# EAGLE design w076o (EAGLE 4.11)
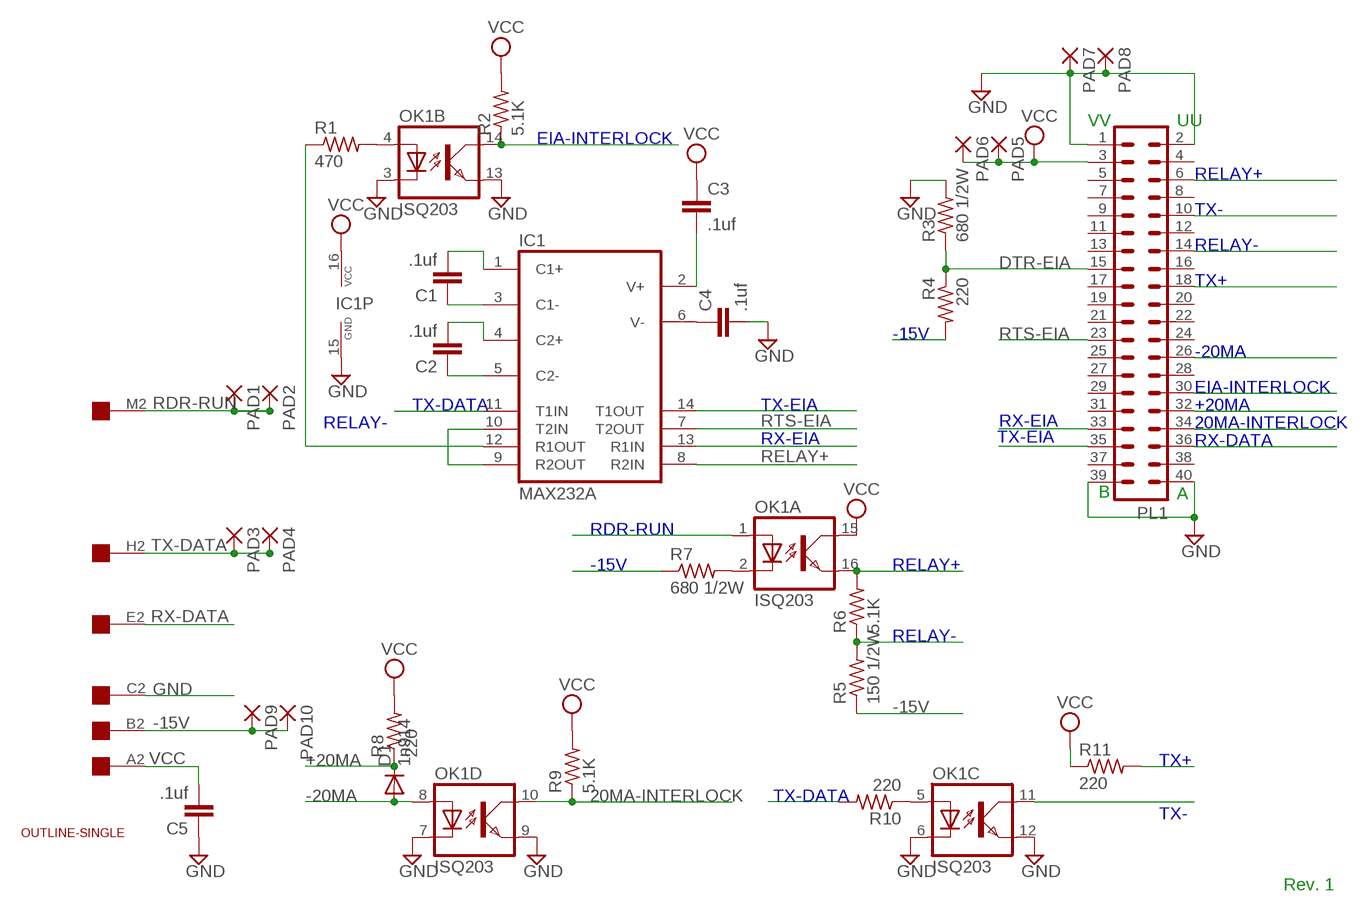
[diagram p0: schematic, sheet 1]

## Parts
C1  .1uf  C-EU050-025X075  [C050-025X075]
C2  .1uf  C-EU050-025X075  [C050-025X075]
C3  .1uf  C-EU050-025X075  [C050-025X075]
C4  .1uf  C-EU050-025X075  [C050-025X075]
C5  .1uf  C-EU050-025X075  [C050-025X075]
D1  1n914  1N4004  [DO41-10]
IC1  MAX232A  MAX232  [DIL16]
OK1  ISQ203  ILQ1  [DIL16]
PAD1  1,6/0,8  [1,6/0,8]
PAD2  1,6/0,8  [1,6/0,8]
PAD3  1,6/0,8  [1,6/0,8]
PAD4  1,6/0,8  [1,6/0,8]
PAD5  1,6/0,8  [1,6/0,8]
PAD6  1,6/0,8  [1,6/0,8]
PAD7  1,6/0,8  [1,6/0,8]
PAD8  1,6/0,8  [1,6/0,8]
PAD9  1,6/0,8  [1,6/0,8]
PAD10  1,6/0,8  [1,6/0,8]
PL1  40H  [40H]
R1  470  R-US_0207/10  [0207/10]
R2  5.1K  R-US_0207/10  [0207/10]
R3  680 1/2W  R-US_0207/12  [0207/12]
R4  220  R-US_0207/10  [0207/10]
R5  150 1/2W  R-US_0207/12  [0207/12]
R6  5.1K  R-US_0207/10  [0207/10]
R7  680 1/2W  R-US_0207/12  [0207/12]
R8  220  R-US_0207/10  [0207/10]
R9  5.1K  R-US_0207/10  [0207/10]
R10  220  R-US_0207/10  [0207/10]
R11  220  R-US_0207/10  [0207/10]
U$1  EDGE-2CONNECTOR  [EDGE-CON2]
U$2  OUTLINE-SINGLE  [SINGLE]

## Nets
20MA-INTERLOCK: OK1.10(D:COL) PL1.34 R9.1
+20MA: D1.C PL1.32 R8.1
-15V [supply]: PAD9.1(P) PAD10.1(P) R4.2 R5.1 R7.1 U$1.B2
-20MA: D1.A OK1.8(D:A) PL1.26
DTR-EIA: PL1.15 R3.1 R4.1
EIA-INTERLOCK: OK1.14(B:COL) PL1.30 R2.1
GND [supply]: C4.2 C5.1 IC1.15(GND) OK1.3(B:C) OK1.6(C:C) OK1.7(D:C) OK1.9(D:EMIT) OK1.12(C:EMIT) OK1.13(B:EMIT) PAD7.1(P) PAD8.1(P) PL1.1 PL1.2 PL1.39 PL1.40 R3.2 U$1.C2
N$1: C2.1 IC1.5(C2-)
N$2: C2.2 IC1.4(C2+)
N$3: C1.2 IC1.1(C1+)
N$4: C1.1 IC1.3(C1-)
N$5: OK1.2(A:C) R7.2
N$6: IC1.9(R2OUT) IC1.10(T2IN)
N$8: IC1.12(R1OUT) R1.1
N$9: C3.2 IC1.2(V+)
N$10: C4.1 IC1.6(V-)
N$11: OK1.4(B:A) R1.2
N$15: OK1.5(C:A) R10.1
RDR-RUN: OK1.1(A:A) PAD1.1(P) PAD2.1(P) U$1.M2
RELAY+: IC1.8(R2IN) OK1.16(A:EMIT) PL1.6 R6.2
RELAY-: PL1.14 R5.2 R6.1
RTS-EIA: IC1.7(T2OUT) PL1.23
RX-DATA: PL1.36 U$1.E2
RX-EIA: IC1.13(R1IN) PL1.33
TX+: PL1.18 R11.2
TX-: OK1.11(C:COL) PL1.10
TX-DATA: IC1.11(T1IN) PAD3.1(P) PAD4.1(P) R10.2 U$1.H2
TX-EIA: IC1.14(T1OUT) PL1.35
VCC [supply]: C3.1 C5.2 IC1.16(VCC) OK1.15(A:COL) PAD5.1(P) PAD6.1(P) PL1.3 R2.2 R8.2 R9.2 R11.1 U$1.A2
Unconnected: PL1.4 PL1.5 PL1.7 PL1.8 PL1.9 PL1.11 PL1.12 PL1.13 PL1.16 PL1.17 PL1.19 PL1.20 PL1.21 PL1.22 PL1.24 PL1.25 PL1.27 PL1.28 PL1.29 PL1.31 PL1.37 PL1.38 U$1.A1 U$1.B1 U$1.C1 U$1.D1 U$1.D2 U$1.E1 U$1.F1 U$1.F2 U$1.H1 U$1.J1 U$1.J2 U$1.K1 U$1.K2 U$1.L1 U$1.L2 U$1.M1 U$1.N1 U$1.N2 U$1.P1 U$1.P2 U$1.R1 U$1.R2 U$1.S1 U$1.S2 U$1.T1 U$1.T2 U$1.U1 U$1.U2 U$1.V1 U$1.V2

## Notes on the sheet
- VV | UU
- EIA-INTERLOCK
- RELAY+
- TX-
- RELAY-
- TX+
- -15V
- -20MA
- EIA-INTERLOCK
- TX-DATA | TX-EIA | +20MA
- RELAY- | RX-EIA | 20MA-INTERLOCK
- RX-EIA | TX-EIA | RX-DATA
- B | A
- RDR-RUN
- -15V | RELAY+
- RELAY-
- TX+
- TX-DATA
- TX-
- Rev. 1

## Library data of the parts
C1-C5 = rcl:C-EU: CAPACITOR, European symbol
D1 = diode:1N4004: DIODE
IC1 = maxim:MAX232: RS232 TRANSEIVER
OK1 = optocoupler:ILQ1: SIEMENS OPTO COUPLER
PAD1-PAD10 = wirepad:1,6/0,8: THROUGH-HOLE PAD
PL1 = con-harting-h:40H: CONNECTOR
R1-R11 = rcl:R-US_: RESISTOR, American symbol
U$1 = dec-con:EDGE-2: Double-Sided DEC edge connector.
U$2 = dec-con:OUTLINE-*: Board outlines for DEC boards.

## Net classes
1 supply: width 0.508 mm

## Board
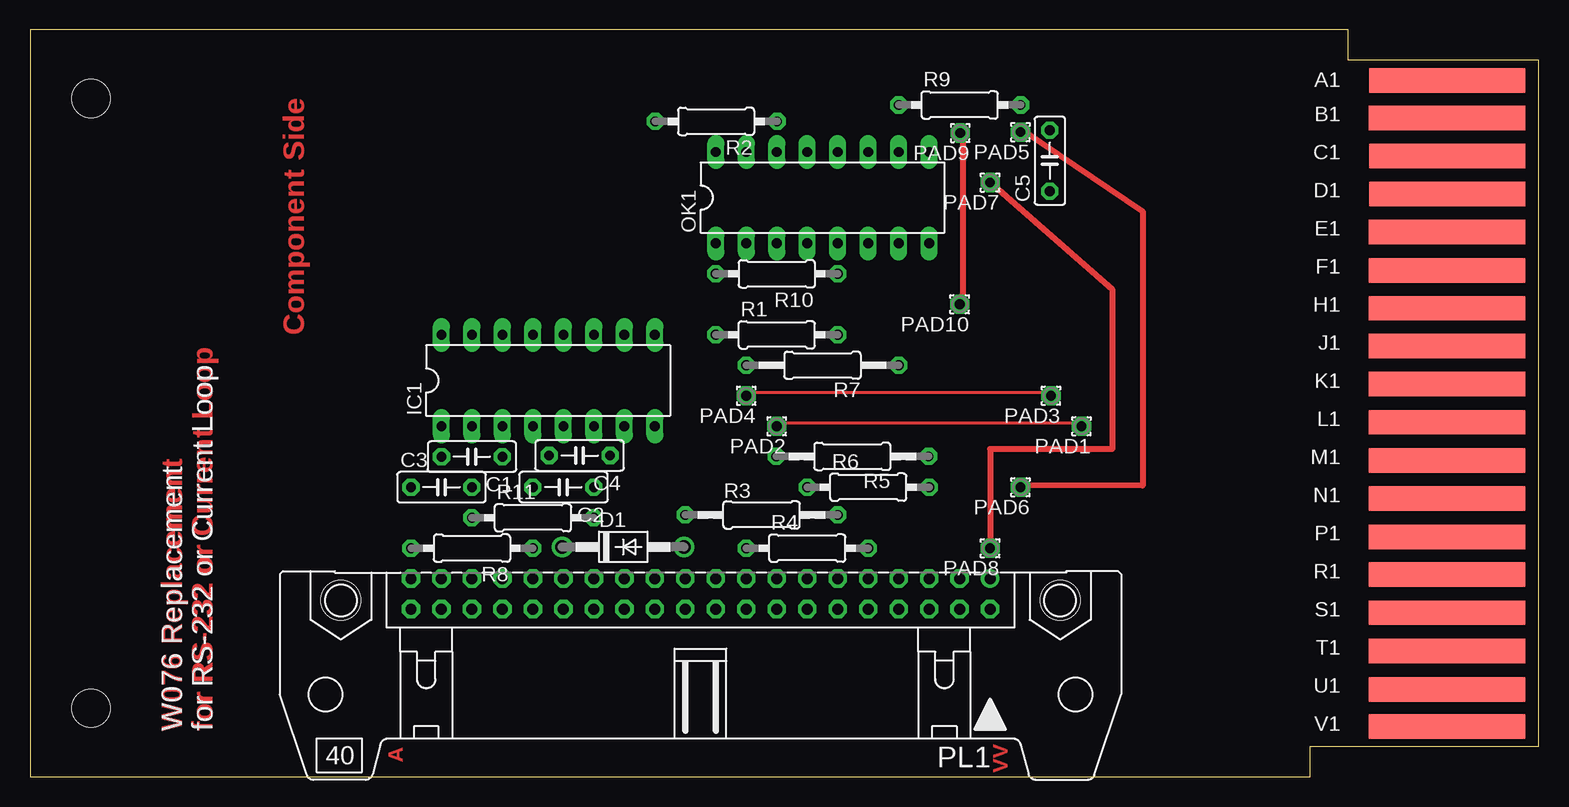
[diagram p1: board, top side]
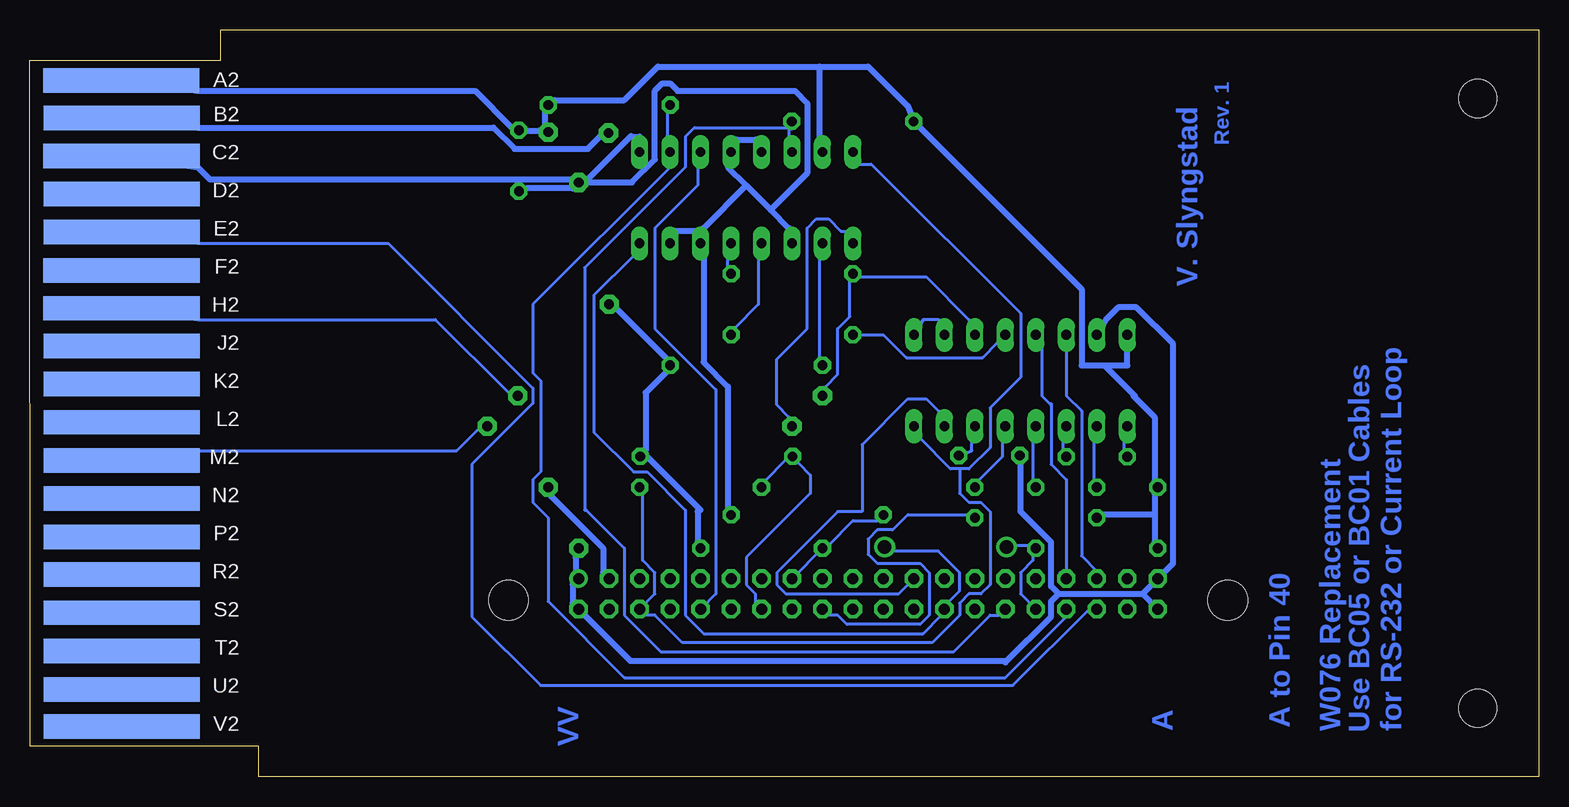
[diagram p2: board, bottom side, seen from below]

Size 125.73 x 62.23 mm. Coordinates in mm from the lower left corner, seen from the top.
Copper layers (1*16): Top 0.035mm / dielectric 1.5mm / Bottom 0.035mm
Design rules "10mils": minimum track width 10mil, minimum drill 28mil, track to track 15mil, track to pad 10mil, pad to pad 10mil, via to via 10mil, smd to smd 10mil, copper to edge 25mil, drill to drill 10mil, minimum pad ring 12mil, minimum via ring 8mil, stop-mask expansion 0mil, vias tented up to drill 0mil, thermal gap 10mil

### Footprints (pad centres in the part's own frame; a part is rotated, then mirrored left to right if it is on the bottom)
C050-025X075 = drill 0.813 octagon: 1 -2.54,0; 2 2.54,0
DO41-10 = drill 1.118 round: A 5.08,0; C -5.08,0
DIL16 = drill 0.813 long: 1 -8.89,-3.81; 2 -6.35,-3.81; 3 -3.81,-3.81; 4 -1.27,-3.81; 5 1.27,-3.81; 6 3.81,-3.81; 7 6.35,-3.81; 8 8.89,-3.81; 9 8.89,3.81; 10 6.35,3.81; 11 3.81,3.81; 12 1.27,3.81; 13 -1.27,3.81; 14 -3.81,3.81; 15 -6.35,3.81; 16 -8.89,3.81
1,6/0,8 = drill 0.813 pad 1.6 octagon: 1 0,0
40H = drill 0.914 round: 1 -24.13,-1.27 | drill 0.914 octagon: 2 -24.13,1.27; 3 -21.59,-1.27; 4 -21.59,1.27; 5 -19.05,-1.27; 6 -19.05,1.27; 7 -16.51,-1.27; 8 -16.51,1.27; 9 -13.97,-1.27; 10 -13.97,1.27; 11 -11.43,-1.27; 12 -11.43,1.27; 13 -8.89,-1.27; 14 -8.89,1.27; 15 -6.35,-1.27; 16 -6.35,1.27; 17 -3.81,-1.27; 18 -3.81,1.27; 19 -1.27,-1.27; 20 -1.27,1.27; 21 1.27,-1.27; 22 1.27,1.27; 23 3.81,-1.27; 24 3.81,1.27; 25 6.35,-1.27; 26 6.35,1.27; 27 8.89,-1.27; 28 8.89,1.27; 29 11.43,-1.27; 30 11.43,1.27; 31 13.97,-1.27; 32 13.97,1.27; 33 16.51,-1.27; 34 16.51,1.27; 35 19.05,-1.27; 36 19.05,1.27; 37 21.59,-1.27; 38 21.59,1.27; 39 24.13,-1.27; 40 24.13,1.27 | hole 3.302: -29.972,0.533; 29.972,0.533
0207/10 = drill 0.813 octagon: 1 -5.08,0; 2 5.08,0
0207/12 = drill 0.813 octagon: 1 -6.35,0; 2 6.35,0
EDGE-CON2 = smd 13.017 x 2.032: A1 7.633,4.207; B1 7.639,7.327; C1 7.636,10.489; D1 7.633,13.665; E1 7.642,16.84; F1 7.642,20.041; H1 7.642,23.19; J1 7.642,26.34; K1 7.642,29.515; L1 7.642,32.69; M1 7.642,35.89; N1 7.642,39.04; P1 7.642,42.24; R1 7.642,45.39; S1 7.642,48.565; T1 7.642,51.74; U1 7.642,54.966; V1 7.642,58.026 | smd 13.017 x 2.032 bottom: A2 7.614,4.207; B2 7.642,7.328; C2 7.617,10.49; D2 7.642,13.665; E2 7.642,16.84; F2 7.617,20.041; H2 7.617,23.19; J2 7.642,26.34; K2 7.642,29.515; L2 7.642,32.69; M2 7.642,35.89; N2 7.642,39.04; P2 7.642,42.24; R2 7.642,45.39; S2 7.642,48.565; T2 7.642,51.74; U2 7.642,54.966; V2 7.642,58.026
SINGLE = hole 3.175: 120.65,56.515; 120.65,5.715

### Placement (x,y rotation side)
C1  36.83,26.67 180 top
C2  44.45,24.13 180 top
C3  34.29,24.13 0 top
C4  45.8,26.77 180 top
C5  84.99,51.33 90 top
D1  49.43,19.15 0 top
IC1  43.18,33.02 0 top
OK1  66.04,48.26 0 top
PAD1  87.63,29.21 180 top
PAD2  62.23,29.21 180 top
PAD3  85.09,31.75 180 top
PAD4  59.69,31.75 180 top
PAD5  82.55,53.72 180 top
PAD6  82.55,24.13 180 top
PAD7  80.01,49.53 180 top
PAD8  80.01,19.05 180 top
PAD9  77.52,53.64 180 top
PAD10  77.47,39.37 180 top
PL1  55.88,15.24 180 top
R1  62.23,36.83 0 top
R2  57.18,54.61 180 top
R3  60.96,21.82 0 top
R4  64.77,19.05 0 top
R5  68.53,26.7 180 top
R6  69.85,24.13 0 top
R7  66.04,34.29 180 top
R8  36.83,19.05 180 top
R9  77.47,55.98 0 top
R10  62.23,41.91 180 top
R11  41.91,21.59 0 top
U$1  125.73,62.23 180 top
U$2  125.73,62.23 180 top

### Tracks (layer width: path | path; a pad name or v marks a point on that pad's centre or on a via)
20MA-INTERLOCK
  Bottom 0.254: R9.1 72.64,55.37 72.64,53.34 OK1.10 72.39,50.8 83.82,39.37 83.82,33.66 83.19,33.02 83.19,25.4 83.82,24.77 83.82,22.86 82.55,21.59 82.55,14.61 76.2,8.26 44.45,8.26 39.37,13.34 PL1.34
+20MA
  Bottom 0.254: PL1.32 43.18,15.24 43.18,17.02 42.16,18.03 42.16,18.54 R8.1 42.42,19.3 43.69,19.3 D1.C
-15V
  Top 0.508: PAD9.1 77.72,53.85 77.72,40.13 PAD10.1
  Bottom 0.508: PAD10.1 76.96,39.12 72.64,34.8 R7.1 72.64,33.78 74.42,32 74.42,27.18 R5.1 74.3,26.67 69.85,22.23 70.1,22.1 70.1,19.56 R4.2 | U$1.B2 111.76,54.1 87.12,54.1 85.34,52.32 79.25,52.32 78.23,53.34 PAD9.1
-20MA
  Bottom 0.254: OK1.8 75.44,43.43 78.74,40.13 78.74,28.7 75.44,25.4 74.42,25.4 74.3,25.4 71.12,22.23 71.12,22.1 71.12,13.46 69.6,11.94 51.31,11.94 49.78,13.46 PL1.26 49.28,14.48 48.26,15.49 48.26,17.02 50.04,18.8 53.85,18.8 D1.A
DTR-EIA
  Bottom 0.254: PL1.15 R4.1 59.18,19.3 57.15,21.34 55.12,21.34 R3.1
EIA-INTERLOCK
  Bottom 0.254: 62.48,54.1 62.48,53.34 OK1.14 | 62.48,54.1 70.36,54.1 71.12,53.34 71.12,50.8 79.5,42.42 79.5,22.23 79.38,22.23 76.2,19.05 76.2,18.41 76.2,18.29 76.2,13.46 73.15,10.41 48.77,10.41 45.72,13.46 44.96,13.46 PL1.30 | R2.1 62.23,53.98 62.48,54.1
GND
  Top 0.508: PAD8.1 80.01,27.3 90.17,27.3 90.17,40.64 PAD7.1
  Bottom 0.508: OK1.13 65.28,53.09 66.8,53.09 OK1.12 67.56,50.8 66.04,49.28 | PAD8.1 80.26,18.29 80.26,17.02 PL1.1 80.52,16 80.52,14.48 PL1.2 75.69,9.65 44.45,9.65 44.45,9.53 40.64,13.34 40.64,14.61 40.01,15.24 | OK1.7 71.88,45.47 70.36,45.47 OK1.6 | 64.01,47.24 66.04,49.28 | 64.01,47.24 62.48,45.72 OK1.3 | 66.04,49.28 69.6,45.72 OK1.6 | OK1.6 69.6,43.18 69.6,34.54 67.56,32.51 67.56,22.35 R3.2 | 64.01,47.24 60.96,50.29 60.96,56.13 61.98,57.15 62.23,57.15 71.75,57.15 72.39,57.78 73.03,57.78 73.66,57.15 73.66,51.44 75.56,49.53 79.38,49.53 PAD7.1 | IC1.15 36.07,38.1 35.05,39.12 33.53,39.12 30.48,36.07 30.48,17.78 PL1.39 33.02,15.24 | 39.88,15.24 33.02,15.24 | 33.02,15.24 PL1.40 | C4.2 43.18,26.16 43.18,22.1 40.64,19.56 40.64,16 40.64,15.88 40.01,15.24 | PAD7.1 79.25,49.78 75.63,53.4 75.56,53.34 74.93,53.34 OK1.9 | C5.1 84.33,49.02 80.52,49.02 PAD7.1 | PAD7.1 80.77,49.78 110.74,49.78 111.76,50.8 U$1.C2 | 40.01,15.24 39.88,15.24 | 40.01,15.24 39.88,15.24
N$1
  Bottom 0.254: IC1.5 44.7,28.19 44.7,26.67 46.74,24.64 C2.1
N$2
  Bottom 0.254: IC1.4 42.16,28.19 42.16,24.64 C2.2
N$3
  Bottom 0.254: IC1.1 34.54,28.19 34.54,27.18 C1.2
N$4
  Bottom 0.254: IC1.3 39.62,28.19 39.62,27.18 C1.1
N$5
  Bottom 0.254: OK1.2 59.94,43.18 59.94,34.8 R7.2
N$6
  Bottom 0.254: IC1.9 51.31,38.1 50.04,38.1 IC1.10
N$8
  Bottom 0.254: 56.64,36.58 R1.1 56.52,36.83 54.61,36.83 52.7,34.92 46.35,34.92 45.09,36.2 IC1.12
N$9
  Bottom 0.254: IC1.2 37.08,28.19 37.08,24.64 C3.2
N$10
  Bottom 0.254: IC1.6 47.24,28.19 47.24,27.18 C4.1
N$11
  Bottom 0.254: OK1.4 65.02,43.18 65.02,39.37 67.06,37.34 R1.2
N$15
  Bottom 0.254: OK1.5 67.56,43.18 67.56,42.42 R10.1
RDR-RUN
  Top 0.254: PAD1.1 86.87,29.46 62.99,29.46 PAD2.1
  Bottom 0.254: OK1.1 57.66,45.47 58.17,45.47 59.18,46.48 60.2,46.48 60.96,45.72 60.96,37.34 63.5,34.8 63.5,30.99 62.48,29.97 PAD2.1 | U$1.M2 111.76,27.18 90.17,27.18 88.39,28.96 PAD1.1
RELAY+
  Bottom 0.254: R6.2 74.68,23.62 74.68,18.03 73.66,17.02 73.66,15.24 PL1.6 74.42,13.46 73.66,13.46 71.37,11.18 50.55,11.18 48.26,13.46 48.26,14.48 47.5,15.24 46.48,15.24 45.72,16 45.72,22.1 46.48,22.86 47.5,22.86 48.26,23.62 48.26,25.65 | 48.26,25.65 49.02,25.65 51.56,28.19 IC1.8 | 48.26,25.65 47.5,25.65 45.72,27.43 45.72,30.73 43.18,33.27 43.18,38.61 55.63,51.05 56.64,51.05 OK1.16
RELAY-
  Bottom 0.254: R6.1 64.52,24.64 62.74,26.42 R5.2 61.72,26.16 60.71,25.15 60.71,23.62 66.04,18.29 66.04,16 65.28,15.24 65.28,14.48 PL1.14
RTS-EIA
  Bottom 0.254: PL1.23 53.34,15.24 62.74,15.24 63.5,16 63.5,17.02 58.42,22.1 56.39,22.1 56.39,27.69 52.58,31.5 51.05,31.5 50.04,30.48 IC1.7
RX-DATA
  Bottom 0.254: PL1.36 37.47,13.97 43.81,7.62 83.19,7.62 88.9,13.34 88.9,26.04 83.82,31.11 83.82,32.38 95.89,44.45 111.76,44.45 U$1.E2
RX-EIA
  Bottom 0.254: 40.7,31.05 41.4,31.75 41.4,35.81 IC1.13 | 40.7,31.05 40.64,30.99 | 39.88,17.02 PL1.33 39.37,17.14 39.37,24.77 40.64,26.04 40.64,31.11 40.7,31.05
TX+
  Bottom 0.254: R11.2 47.5,21.84 52.58,21.84 53.85,20.57 55.12,20.57 55.88,19.81 55.88,18.54 55.12,17.78 51.56,17.78 50.8,17.02 50.8,13.46 51.56,12.7 57.66,12.7 58.42,13.46 59.18,13.46 PL1.18
TX-
  Bottom 0.254: OK1.11 70.1,50.8 70.1,49.28 73.66,45.72 73.66,37.34 68.58,32.26 68.58,15.24 PL1.10
TX-DATA
  Top 0.254: PAD4.1 60.45,32 84.33,32 PAD3.1
  Bottom 0.254: IC1.11 47.5,38.1 51.05,41.66 56.64,41.66 R10.2 57.4,41.4 57.4,38.35 58.42,37.34 58.42,33.53 59.44,32.51 PAD4.1 | U$1.H2 111.76,38.1 91.95,38.1 85.85,32 PAD3.1
TX-EIA
  Bottom 0.254: IC1.14 39.37,35.56 39.37,31.75 38.1,30.48 38.1,18.41 36.83,17.14 PL1.35
VCC
  Top 0.508: PAD6.1 82.55,24.16 83.13,24.28 92.71,24.26 92.71,47.12 82.8,53.85 PAD5.1
  Bottom 0.508: PL1.3 77.98,17.02 77.98,19.05 82.3,23.37 PAD6.1 | 32,21.84 32,23.62 C3.1 32,24.64 32,29.97 33.72,31.69 | 32,21.84 32,19.56 R8.2 | 59.94,59.18 73.41,59.18 76.2,56.39 82.04,56.39 R9.2 82.8,55.37 82.8,54.36 PAD5.1 83.31,53.85 84.33,53.85 C5.2 85.6,54.1 88.65,57.15 111.76,57.15 U$1.A2 | 59.94,59.18 55.88,59.18 52.58,55.88 R2.2 38.1,40.64 38.1,34.29 36.2,34.29 | 59.94,59.18 59.94,53.34 OK1.15 | 33.72,31.69 33.78,31.75 | 32,21.84 36.32,21.84 R11.1 | IC1.16 34.29,34.29 36.2,34.29 | 36.2,34.29 33.66,31.75 33.72,31.69

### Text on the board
Top: Component Side | W076 Replacement | for RS-232 or Current Loop | A | VV
Bottom: Rev. 1 | V. Slyngstad | for RS-232 or Current Loop | Use BC05 or BC01 Cables | W076 Replacement | A to Pin 40 | A | VV
tPlace: W076 Replacement | for RS-232 or Current Loop
_tplace: .1uf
